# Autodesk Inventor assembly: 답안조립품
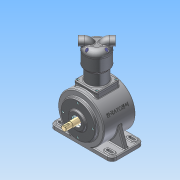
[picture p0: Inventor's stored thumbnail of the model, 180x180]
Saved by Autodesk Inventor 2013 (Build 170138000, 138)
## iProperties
Created: 2015-06
Part Number: 답안조립품
Document SubType Name: Assembly
Designer: Administrator
Author: Administrator
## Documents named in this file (8)
- C:\Users\Administrator\Desktop\450606V1014\답안조립품.iam
- C:\Users\Administrator\Desktop\450606V1014\본체.ipt
- C:\Users\Administrator\Desktop\450606V1014\메인 크랭크 축-구동부.ipt
- C:\Users\Administrator\Desktop\450606V1014\메인커버.ipt
- C:\Users\Administrator\Desktop\450606V1014\베어링 6204.ipt
- C:\Users\Administrator\Desktop\450606V1014\크랭크 서브축.ipt
- C:\Users\Administrator\Desktop\450606V1014\실린더.ipt
- C:\Users\Administrator\Desktop\450606V1014\실린더헤드.ipt
